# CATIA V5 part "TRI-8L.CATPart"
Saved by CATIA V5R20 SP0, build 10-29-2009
Part number: _TRI-8L
Definition: NONE
Nomenclature: _TRI-8L
Source: Unknown
Description: PART-_TRI-8L-DESC
Bounding box of the stored display mesh (mm): x 0 to 15, y -4 to 4, z -4 to 4
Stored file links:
  C:\Users\Utente\Desktop\IO LAVORO\3D X SITO CF\X SITO\PLASTICA\TRI\TRI-8L.CATPart
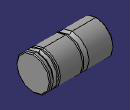
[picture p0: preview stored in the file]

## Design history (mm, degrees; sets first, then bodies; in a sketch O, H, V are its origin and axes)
Body1 "_TRI-8L" (main body)
  Solid1: solid without history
